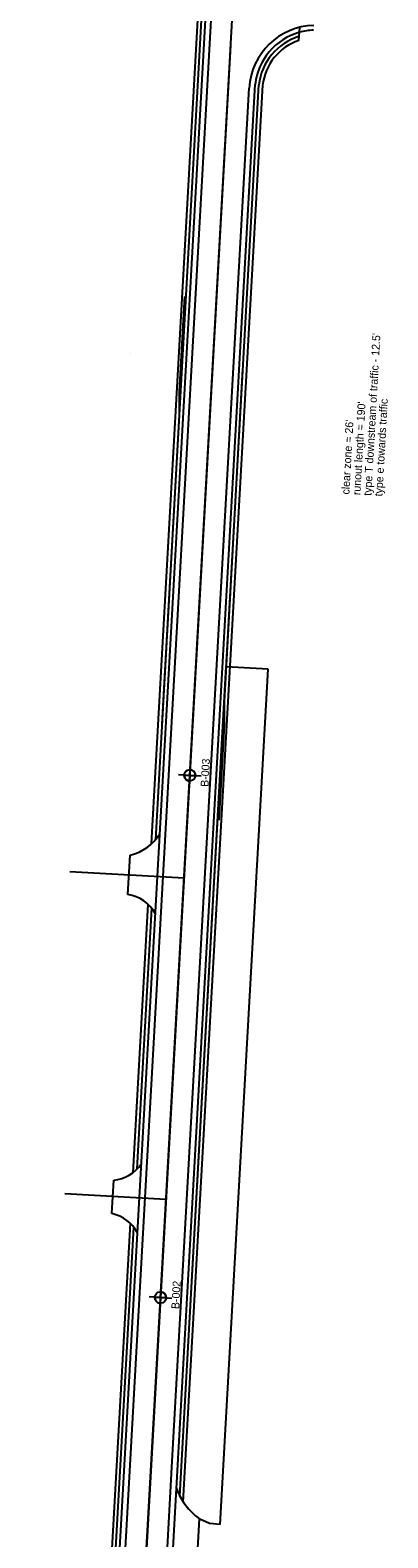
# Model space of a CAD drawing. Extents: x 1973866 to 1974130, y 734965 to 738427.
# Drawn here: x 1973884 to 1974073, y 736062 to 736854 of the extents above; entities that cross this region are included whole.
import ezdxf

# ---------------------------------------------------------------- set-up
doc = ezdxf.new("R2010")
doc.units = 0
for name, color, linetype in [('_CIVIL_CONSTRUCTION', 7, 'Continuous'), ('CM_Corridor_Range_Conceptual', 7, 'Continuous'), ('DR_P_Cells', 7, 'Continuous'), ('DR_P_Headwall', 7, 'Continuous'), ('DR_P_Storm_Sewer', 7, 'Continuous'), ('DR_X_Cells', 7, 'Continuous'), ('DR_X_Storm_Sewer', 7, 'Continuous'), ('GK_Drainage_Nodes', 7, 'Continuous'), ('MD_P_ACIC_B', 7, 'Continuous'), ('MD_P_AGB_T', 7, 'Continuous'), ('MD_P_Surface_Aggregate_Base', 7, 'Continuous'), ('MD_P_Surface_Asphalt_Concrete_Base', 7, 'Continuous'), ('PV_P_Saw_Cut_Line', 7, 'Continuous'), ('PV_P_Shoulder', 7, 'Continuous'), ('SC_Scratch1', 7, 'Continuous')]:
    doc.layers.add(name, color=color, linetype=linetype)

msp = doc.modelspace()

# ---------------------------------------------------------------- linework, layer by layer
at = {"layer": '_CIVIL_CONSTRUCTION'}
for p, q in [((1973935.87, 736399.97), (1973937.02, 736420.63)), ((1973927.45, 736232.14), (1973928.44, 736249.76))]:
    msp.add_line(p, q, dxfattribs=at)
for centre, radius, start, end in [((1973931.38, 736444.99), 25, 283.04944, 328.4316), ((1973932.75, 736380.22), 20, 28.57757, 81.05007), ((1973926.55, 736269.67), 20, 275.41617, 325.00091), ((1973923.35, 736212.56), 20, 28.57757, 78.16231)]:
    msp.add_arc(centre, radius, start, end, dxfattribs=at)
at = {"layer": 'CM_Corridor_Range_Conceptual'}
for p, q in [((1973948.38, 736426.66), (1973992.44, 737212.16)), ((1974025.91, 736848.99), (1974026.03, 736851.13)), ((1973965.02, 736080.57), (1974006.81, 736825.49)), ((1973938.68, 736253.77), (1973946.59, 736394.66)), ((1973914.65, 735825.29), (1973937.18, 736227.01))]:
    msp.add_line(p, q, dxfattribs=at)
msp.add_arc((1974034.92, 736822.16), 28.3, 108.56115, 173.62605, dxfattribs=at)
at = {"layer": 'DR_P_Cells'}
msp.add_line((1973884.41, 734964.92), (1974010.42, 737211.15), dxfattribs=at)
at = {"layer": 'DR_P_Headwall'}
for p, q in [((1973905.3, 736412.05), (1973965.4, 736408.68)), ((1973902.65, 736242.69), (1973955.92, 736239.71))]:
    msp.add_line(p, q, dxfattribs=at)
at = {"layer": 'DR_P_Storm_Sewer'}
for p, q in [((1973918.64, 735825.07), (1973996.44, 737211.94)), ((1973961.41, 736087.61), (1974002.82, 736825.75)), ((1973956.55, 736000.91), (1973961.41, 736087.61))]:
    msp.add_line(p, q, dxfattribs=at)
msp.add_arc((1974034.92, 736822.16), 32.3, 105.74545, 173.62605, dxfattribs=at)
at = {"layer": 'DR_X_Cells'}
for p, q in [((1973950.51, 736428.89), (1973994.44, 737212.05)), ((1974026.03, 736851.13), (1974026.15, 736853.25)), ((1973963.19, 736083.65), (1974004.81, 736825.61)), ((1973940.79, 736255.62), (1973948.47, 736392.58)), ((1973916.64, 735825.18), (1973939.07, 736224.93))]:
    msp.add_line(p, q, dxfattribs=at)
msp.add_arc((1974034.92, 736822.16), 30.3, 107.05397, 173.62605, dxfattribs=at)
at = {"layer": 'DR_X_Storm_Sewer'}
for p, q in [((1973989.95, 736846.26), (1973947.03, 736081.21)), ((1973947.03, 736081.21), (1973932.62, 735824.28))]:
    msp.add_line(p, q, dxfattribs=at)
at = {"layer": 'GK_Drainage_Nodes'}
msp.add_line((1974026.15, 736853.25), (1974026.3, 736855.87), dxfattribs=at)
msp.add_arc((1974034.65, 736821.88), 32.5, 91.92542, 105.15888, dxfattribs=at)
at = {"layer": 'MD_P_ACIC_B'}
for centre in [(1973968.42, 736462.56), (1973953.02, 736188)]:
    msp.add_circle(centre, 0.05, dxfattribs=at)
at = {"layer": 'MD_P_Surface_Aggregate_Base'}
for p, q in [((1973995.73, 736663.63), (1973996.43, 736676.11)), ((1973986.63, 736501.39), (1973995.73, 736663.63)), ((1973986.67, 736488.87), (1973986.63, 736501.39)), ((1973983.87, 736438.94), (1973986.67, 736488.87))]:
    msp.add_line(p, q, dxfattribs=at)
at = {"layer": 'MD_P_Surface_Asphalt_Concrete_Base'}
for p, q in [((1973968.42, 736462.56), (1973962.43, 736462.9)), ((1973965.43, 736462.73), (1973968.42, 736462.56)), ((1973968.42, 736462.56), (1973968.09, 736456.57)), ((1973968.42, 736462.56), (1973968.25, 736459.57)), ((1973968.42, 736462.56), (1973968.76, 736468.55)), ((1973968.42, 736462.56), (1973968.59, 736465.56)), ((1973968.42, 736462.56), (1973974.41, 736462.23)), ((1973971.42, 736462.4), (1973968.42, 736462.56)), ((1973953.02, 736188), (1973953.36, 736193.99)), ((1973953.02, 736188), (1973947.03, 736188.33)), ((1973950.02, 736188.16), (1973953.02, 736188)), ((1973953.02, 736188), (1973952.68, 736182)), ((1973953.02, 736188), (1973952.85, 736185)), ((1973953.02, 736188), (1973953.19, 736190.99)), ((1973953.02, 736188), (1973959.01, 736187.66)), ((1973956.02, 736187.83), (1973953.02, 736188))]:
    msp.add_line(p, q, dxfattribs=at)
for centre in [(1973968.42, 736462.56), (1973953.02, 736188)]:
    msp.add_circle(centre, 3, dxfattribs=at)
for centre, start, end in [((1973968.42, 736462.56), 176.78924, 266.78924), ((1973968.42, 736462.56), 356.78924, 86.78924), ((1973953.02, 736188), 176.78924, 266.78924), ((1973953.02, 736188), 356.78924, 86.78924)]:
    msp.add_arc(centre, 3, start, end, dxfattribs=at)
at = {"layer": 'PV_P_Saw_Cut_Line'}
for p, q in [((1973962.97, 736664.44), (1973965.77, 736714.36)), ((1973937.47, 736684.22), (1973937.49, 736684.22)), ((1973963.02, 736651.91), (1973962.97, 736664.44)), ((1973954.62, 736502.15), (1973963.02, 736651.91)), ((1973953.92, 736489.67), (1973954.62, 736502.15))]:
    msp.add_line(p, q, dxfattribs=at)
at = {"layer": 'PV_P_Shoulder'}
for p, q in [((1973963.19, 736083.65), (1973987.65, 736519.58)), ((1973984.38, 736068.63), (1974009.61, 736518.34)), ((1974009.61, 736518.34), (1973987.65, 736519.58)), ((1973978.76, 736069.21), (1973973.74, 736071.54)), ((1973984.38, 736068.63), (1973978.76, 736069.21))]:
    msp.add_line(p, q, dxfattribs=at)
msp.add_arc((1973994.15, 736099.97), 35, 207.79196, 234.32793, dxfattribs=at)
at = {"layer": 'SC_Scratch1'}
for p, q in [((1973921.63, 735824.9), (1973999.43, 737211.77)), ((1973959.21, 736101.93), (1973999.71, 736823.86)), ((1973953.84, 736006.28), (1973959.21, 736101.93)), ((1973971.47, 736034.74), (1973973.54, 736071.68))]:
    msp.add_line(p, q, dxfattribs=at)
for centre, start, end in [((1974034.65, 736821.88), 91.55353, 176.78924), ((1973994.15, 736099.97), 200.68475, 233.91089)]:
    msp.add_arc(centre, 35, start, end, dxfattribs=at)

# ---------------------------------------------------------------- texts
at = {"layer": 'MD_P_AGB_T'}
for s, p in [("type T downstream of traffic - 12.5'", (1974064.02, 736609.48)), ('type e towards traffic', (1974069.81, 736609.15)), ("runout length = 190'", (1974058.22, 736609.8)), ("clear zone = 26'", (1974052.42, 736610.13))]:
    msp.add_text(s, height=4.1667, rotation=86.78924, dxfattribs=at).set_placement(p)
at = {"layer": 'SC_Scratch1'}
for s, p in [('B-003', (1973978.26, 736456.41)), ('B-002', (1973962.86, 736181.85))]:
    msp.add_text(s, height=4.167, rotation=86.78924, dxfattribs=at).set_placement(p)

doc.saveas('drawing.dxf')
